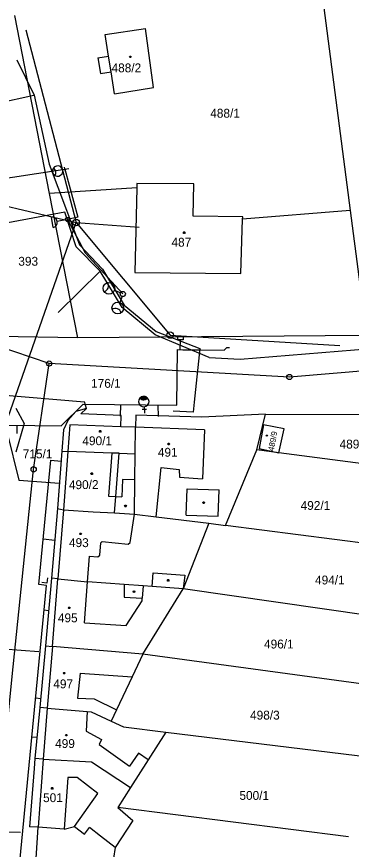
# Model space of a CAD drawing. Extents: x -639621 to -639329, y -1192893 to -1192488.
# Drawn here: x -639497.3 to -639433, y -1192813.4 to -1192653.7 of the extents above; entities that cross this region are included whole.
import ezdxf

# ---------------------------------------------------------------- set-up
doc = ezdxf.new("R2010")
doc.units = 0
for name, color, linetype in [('Vrstva 1', 7, 'Continuous'), ('Vrstva 19', 7, 'Continuous'), ('Vrstva 2', 7, 'Continuous'), ('Vrstva 20', 7, 'Continuous'), ('Vrstva 21', 7, 'Continuous'), ('Vrstva 22', 7, 'Continuous'), ('Vrstva 24', 7, 'Continuous'), ('Vrstva 25', 7, 'Continuous'), ('Vrstva 4', 7, 'Continuous'), ('Vrstva 5', 7, 'Continuous')]:
    doc.layers.add(name, color=color, linetype=linetype)

msp = doc.modelspace()

# ---------------------------------------------------------------- linework, layer by layer
at = {"layer": 'Vrstva 1'}
for p, q in [((-639439.54, -1192642.21), (-639433.22, -1192690.86)), ((-639490.92, -1192687.58), (-639497.61, -1192653.45)), ((-639480.26, -1192657.1), (-639472.54, -1192655.97)), ((-639470.96, -1192667.29), (-639472.54, -1192655.97)), ((-639479.61, -1192661.25), (-639480.26, -1192657.1)), ((-639481.67, -1192661.58), (-639479.61, -1192661.25)), ((-639481.67, -1192661.58), (-639481.19, -1192664.63)), ((-639481.19, -1192664.63), (-639479.13, -1192664.31)), ((-639478.46, -1192668.51), (-639479.13, -1192664.31)), ((-639478.46, -1192668.51), (-639470.96, -1192667.29)), ((-639474.2, -1192686.51), (-639490.92, -1192687.58)), ((-639474.18, -1192685.67), (-639474.2, -1192686.51)), ((-639463.27, -1192685.77), (-639474.18, -1192685.67)), ((-639463.37, -1192691.93), (-639463.27, -1192685.77)), ((-639485.5, -1192715.26), (-639490.92, -1192687.58)), ((-639453.87, -1192692.08), (-639463.37, -1192691.93)), ((-639433.22, -1192690.86), (-639453.88, -1192692.51)), ((-639433.22, -1192690.86), (-639430.11, -1192714.81)), ((-639453.88, -1192692.51), (-639453.87, -1192692.08)), ((-639485.5, -1192715.26), (-639500.89, -1192715.05)), ((-639430.11, -1192714.81), (-639485.5, -1192715.26)), ((-639501.84, -1192726.06), (-639484.21, -1192727.56)), ((-639483.84, -1192728.82), (-639484.21, -1192727.56)), ((-639497.38, -1192728.76), (-639495.79, -1192731.74)), ((-639485.89, -1192729.44), (-639487.46, -1192731.13)), ((-639483.84, -1192728.82), (-639485.89, -1192729.44)), ((-639484.96, -1192729.88), (-639483.84, -1192728.82)), ((-639477.18, -1192730.19), (-639484.96, -1192729.88)), ((-639477.27, -1192732.34), (-639477.18, -1192730.19)), ((-639474.39, -1192730.12), (-639474.46, -1192732.44)), ((-639461.71, -1192730.47), (-639474.39, -1192730.12)), ((-639449.52, -1192729.95), (-639461.71, -1192730.47)), ((-639451.15, -1192736.79), (-639449.52, -1192729.95)), ((-639449.52, -1192729.95), (-639428.21, -1192730.01)), ((-639495.79, -1192731.74), (-639497.4, -1192737.18)), ((-639487.46, -1192731.13), (-639488.23, -1192732.93)), ((-639488.23, -1192732.93), (-639488.56, -1192737.03)), ((-639474.46, -1192732.44), (-639477.27, -1192732.34)), ((-639474.51, -1192737.54), (-639474.46, -1192732.44)), ((-639449.89, -1192731.98), (-639450.7, -1192736.53)), ((-639445.94, -1192732.75), (-639449.89, -1192731.98)), ((-639446.92, -1192737.34), (-639445.94, -1192732.75)), ((-639450.7, -1192736.53), (-639446.92, -1192737.34)), ((-639488.56, -1192737.03), (-639489.43, -1192748.02)), ((-639488.56, -1192737.03), (-639487.41, -1192737.07)), ((-639478.97, -1192737.38), (-639487.41, -1192737.07)), ((-639477.57, -1192737.43), (-639478.97, -1192737.38)), ((-639478.21, -1192745.71), (-639477.57, -1192737.43)), ((-639474.56, -1192742.54), (-639474.51, -1192737.54)), ((-639457.18, -1192751.25), (-639451.15, -1192736.79)), ((-639446.92, -1192737.34), (-639451.15, -1192736.79)), ((-639420.45, -1192740.76), (-639446.92, -1192737.34)), ((-639474.62, -1192749.07), (-639474.56, -1192742.54)), ((-639478.46, -1192748.87), (-639478.21, -1192745.71)), ((-639489.43, -1192748.02), (-639490.57, -1192761.34)), ((-639489.43, -1192748.02), (-639488.29, -1192748.27)), ((-639488.29, -1192748.27), (-639482.55, -1192748.66)), ((-639482.55, -1192748.66), (-639478.46, -1192748.87)), ((-639478.46, -1192748.87), (-639474.62, -1192749.07)), ((-639474.62, -1192749.07), (-639470.47, -1192749.61)), ((-639470.47, -1192749.61), (-639460.35, -1192750.84)), ((-639460.35, -1192750.84), (-639465.28, -1192763.39)), ((-639460.35, -1192750.84), (-639457.18, -1192751.25)), ((-639422.16, -1192755.8), (-639457.18, -1192751.25)), ((-639490.57, -1192761.34), (-639491.69, -1192774.35)), ((-639489.32, -1192761.47), (-639490.57, -1192761.34)), ((-639489.32, -1192761.47), (-639483.65, -1192762.07)), ((-639476.6, -1192762.58), (-639483.65, -1192762.07)), ((-639472.96, -1192762.84), (-639476.6, -1192762.58)), ((-639473.03, -1192775.94), (-639465.28, -1192763.39)), ((-639471.23, -1192762.96), (-639472.96, -1192762.84)), ((-639465.28, -1192763.39), (-639471.23, -1192762.96)), ((-639423.61, -1192769.39), (-639465.28, -1192763.39)), ((-639491.69, -1192774.35), (-639492.8, -1192786.16)), ((-639491.69, -1192774.35), (-639490.4, -1192774.46)), ((-639473.03, -1192775.94), (-639490.4, -1192774.46)), ((-639473.03, -1192775.94), (-639475.11, -1192780.31)), ((-639425.4, -1192782.45), (-639473.03, -1192775.94)), ((-639475.11, -1192780.31), (-639478.12, -1192786.62)), ((-639492.8, -1192786.16), (-639493.73, -1192795.97)), ((-639491.37, -1192786.28), (-639492.8, -1192786.16)), ((-639491.37, -1192786.28), (-639483.72, -1192786.91)), ((-639483.72, -1192786.91), (-639482.92, -1192786.98)), ((-639482.92, -1192786.98), (-639479.14, -1192788.77)), ((-639478.12, -1192786.62), (-639479.14, -1192788.77)), ((-639479.14, -1192788.77), (-639476.76, -1192789.89)), ((-639476.76, -1192789.89), (-639468.6, -1192790.89)), ((-639468.6, -1192790.89), (-639472.03, -1192796.23)), ((-639468.6, -1192790.89), (-639420.82, -1192796.76)), ((-639493.73, -1192795.97), (-639493.91, -1192797.87)), ((-639492.15, -1192796.06), (-639493.73, -1192795.97)), ((-639492.15, -1192796.06), (-639482.87, -1192796.56)), ((-639482.87, -1192796.56), (-639475.39, -1192801.48)), ((-639472.03, -1192796.23), (-639475.39, -1192801.48)), ((-639493.91, -1192797.87), (-639494.79, -1192809.03)), ((-639475.39, -1192801.48), (-639477.86, -1192805.33)), ((-639477.86, -1192805.33), (-639474.95, -1192807.86)), ((-639433.54, -1192810.98), (-639477.86, -1192805.33)), ((-639474.95, -1192807.86), (-639478.34, -1192813)), ((-639493.12, -1192809.14), (-639494.79, -1192809.03)), ((-639494.4, -1192827.84), (-639493.12, -1192809.14)), ((-639478.34, -1192813), (-639481.06, -1192829.36))]:
    msp.add_line(p, q, dxfattribs=at)
at = {"layer": 'Vrstva 19'}
for points in [[(-639355.75, -1192712.63), (-639405.3, -1192719.5), (-639444.91, -1192722.8), (-639491, -1192720.22), (-639511.44, -1192713.33)], [(-639498.88, -1192834.04), (-639503.12, -1192829.95), (-639498.12, -1192780.2), (-639493.99, -1192740.51), (-639491, -1192720.22)]]:
    msp.add_lwpolyline(points, dxfattribs=at)
for centre in [(-639491, -1192720.22), (-639444.91, -1192722.8), (-639493.99, -1192740.51)]:
    msp.add_circle(centre, 0.5, dxfattribs=at)
at = {"layer": 'Vrstva 20'}
for points in [[(-639495.51, -1192656.21), (-639485.82, -1192693.16)], [(-639509.77, -1192687.52), (-639485.82, -1192693.16)], [(-639500.78, -1192735.77), (-639485.82, -1192693.16)], [(-639485.83, -1192693.15), (-639467.78, -1192714.75)], [(-639485.82, -1192693.16), (-639473.73, -1192694.06)], [(-639467.78, -1192714.75), (-639435.22, -1192716.73)]]:
    msp.add_lwpolyline(points, dxfattribs=at)
for centre in [(-639485.82, -1192693.16), (-639467.78, -1192714.75)]:
    msp.add_circle(centre, 0.62, dxfattribs=at)
at = {"layer": 'Vrstva 21'}
for points in [[(-639497.23, -1192661.98), (-639493.87, -1192668.77), (-639490.99, -1192681.96), (-639487.71, -1192690.82), (-639485.18, -1192697.44), (-639480.79, -1192702.15), (-639476.64, -1192709.03), (-639470.46, -1192714.1), (-639462.07, -1192717.33), (-639463.18, -1192727.64)], [(-639463.18, -1192727.64), (-639463.38, -1192729.53), (-639467.23, -1192729.37)]]:
    msp.add_lwpolyline(points, dxfattribs=at)
at = {"layer": 'Vrstva 22'}
for p, q in [((-639488.44, -1192683.03), (-639487.24, -1192682.79)), ((-639487.89, -1192683.37), (-639488.06, -1192682.54)), ((-639487.88, -1192692.68), (-639489.47, -1192692.98)), ((-639487.49, -1192692.58), (-639484.1, -1192699)), ((-639484.1, -1192699), (-639476.89, -1192706.87)), ((-639477.34, -1192706.64), (-639478.49, -1192706.18)), ((-639477.02, -1192707.35), (-639477.44, -1192708.52)), ((-639473.61, -1192726.87), (-639472.15, -1192726.85)), ((-639473.47, -1192726.74), (-639472.27, -1192726.72)), ((-639472.27, -1192726.96), (-639473.44, -1192726.98)), ((-639472.42, -1192726.61), (-639473.29, -1192726.61)), ((-639473.29, -1192726.61), (-639473.28, -1192727.08)), ((-639473.28, -1192727.08), (-639472.42, -1192727.06)), ((-639473.09, -1192726.55), (-639473.05, -1192727.13)), ((-639472.61, -1192726.55), (-639473.06, -1192726.56)), ((-639472.86, -1192726.54), (-639472.85, -1192727.16)), ((-639472.6, -1192727.15), (-639472.61, -1192726.55)), ((-639472.42, -1192727.06), (-639472.42, -1192726.61)), ((-639472.27, -1192726.72), (-639472.27, -1192726.96)), ((-639473.05, -1192727.13), (-639472.6, -1192727.15)), ((-639472.75, -1192728.5), (-639472.74, -1192729.72)), ((-639473.19, -1192728.97), (-639472.34, -1192728.97))]:
    msp.add_line(p, q, dxfattribs=at)
for points in [[(-639503.01, -1192690.37), (-639503.57, -1192685.33), (-639487.98, -1192682.94)], [(-639487.98, -1192682.93), (-639485.53, -1192692.16), (-639487.49, -1192692.58)], [(-639490.65, -1192692.16), (-639490.28, -1192694.12)]]:
    msp.add_lwpolyline(points, dxfattribs=at)
for centre, radius in [((-639487.49, -1192692.58), 0.4), ((-639479.54, -1192705.79), 1.12), ((-639476.89, -1192706.87), 0.5), ((-639477.85, -1192709.56), 1.12)]:
    msp.add_circle(centre, radius, dxfattribs=at)
for centre, radius, start, end in [((-639489.39, -1192683.31), 1, 238.9018, 238.054), ((-639490.71, -1192683.59), 1, 324.1058, 60.0135), ((-639490.46, -1192693.14), 1, 10.7156, 100.7156), ((-639490.46, -1192693.14), 1, 280.7156, 10.7156), ((-639480.73, -1192705.31), 1.12, 282.4447, 33.157), ((-639478.28, -1192710.77), 1.12, 15.2433, 125.9557), ((-639472.85, -1192727.51), 1, 138.1032, 137.2554), ((-639472.88, -1192726.16), 1, 223.3072, 319.2149)]:
    msp.add_arc(centre, radius, start, end, dxfattribs=at)
at = {"layer": 'Vrstva 24'}
for p, q in [((-639465.86, -1192717.55), (-639465.84, -1192715.65)), ((-639477.34, -1192730.33), (-639477.27, -1192728.09)), ((-639470.06, -1192730.34), (-639470.08, -1192728.17)), ((-639497.18, -1192733.61), (-639497.16, -1192732.07)), ((-639492.99, -1192762.57), (-639490.69, -1192738.71)), ((-639490.69, -1192738.71), (-639488.71, -1192738.94)), ((-639492.14, -1192753.8), (-639489.95, -1192754.11)), ((-639497.84, -1192828.49), (-639491.5, -1192762.76)), ((-639491.5, -1192762.76), (-639492.99, -1192762.57)), ((-639491.95, -1192767.45), (-639491.11, -1192767.56)), ((-639493.58, -1192784.31), (-639492.59, -1192784.42)), ((-639494.3, -1192791.81), (-639493.31, -1192791.88))]:
    msp.add_line(p, q, dxfattribs=at)
for points in [[(-639515.87, -1192709.9), (-639519.84, -1192721.02), (-639516.94, -1192722.05), (-639506.44, -1192723.65), (-639501.22, -1192727.82), (-639498.84, -1192732.05), (-639488.74, -1192732.16), (-639484.49, -1192728.01), (-639466.5, -1192728.21)], [(-639466.31, -1192715.65), (-639466.3, -1192715.05), (-639465.3, -1192715.06), (-639465.31, -1192715.66), (-639466.31, -1192715.65)], [(-639466.5, -1192728.21), (-639466.36, -1192717.55), (-639457.42, -1192717.66), (-639456.89, -1192717.15), (-639456.39, -1192717.16)], [(-639465.36, -1192717.56), (-639457.42, -1192717.66), (-639456.89, -1192717.15), (-639456.39, -1192717.16)]]:
    msp.add_lwpolyline(points, dxfattribs=at)
at = {"layer": 'Vrstva 25'}
for p, q in [((-639493.98, -1192668.81), (-639508.15, -1192671.96)), ((-639489.28, -1192710.42), (-639481.2, -1192702.48)), ((-639454.38, -1192719.35), (-639371.54, -1192712.72)), ((-639460.28, -1192719.08), (-639454.38, -1192719.35)), ((-639499.05, -1192733.48), (-639496.86, -1192742.59)), ((-639496.86, -1192742.59), (-639489.05, -1192743.18)), ((-639491.31, -1192761.32), (-639491.43, -1192762.32)), ((-639491.43, -1192762.32), (-639492.43, -1192762.21)), ((-639499.78, -1192774.9), (-639492.99, -1192775.4)), ((-639503.1, -1192809.83), (-639496.5, -1192810.09))]:
    msp.add_line(p, q, dxfattribs=at)
msp.add_lwpolyline([(-639460.28, -1192719.08), (-639470.7, -1192714.68), (-639477.01, -1192709.49), (-639481.2, -1192702.48), (-639485.83, -1192697.85), (-639487.99, -1192691.19), (-639504.1, -1192694.19)], dxfattribs=at)
at = {"layer": 'Vrstva 4'}
for p, q in [((-639479.13, -1192664.31), (-639479.61, -1192661.25)), ((-639474.2, -1192686.51), (-639474.54, -1192702.75)), ((-639454.21, -1192702.93), (-639453.88, -1192692.51)), ((-639474.54, -1192702.75), (-639454.21, -1192702.93)), ((-639487.02, -1192731.99), (-639487.41, -1192737.07)), ((-639477.27, -1192732.34), (-639487.02, -1192731.99)), ((-639461.21, -1192732.93), (-639474.46, -1192732.44)), ((-639461.21, -1192732.93), (-639461.57, -1192742.35)), ((-639487.41, -1192737.07), (-639488.29, -1192748.27)), ((-639478.97, -1192737.38), (-639479.61, -1192745.66)), ((-639477.57, -1192737.43), (-639474.51, -1192737.54)), ((-639470.47, -1192749.61), (-639469.51, -1192740.17)), ((-639469.51, -1192740.17), (-639466.04, -1192740.52)), ((-639466.04, -1192740.52), (-639466, -1192742)), ((-639476.96, -1192742.45), (-639477.08, -1192745.75)), ((-639474.56, -1192742.54), (-639476.96, -1192742.45)), ((-639466, -1192742), (-639461.57, -1192742.35)), ((-639464.7, -1192749.28), (-639464.52, -1192744.24)), ((-639464.52, -1192744.24), (-639458.41, -1192744.46)), ((-639458.59, -1192749.49), (-639458.41, -1192744.46)), ((-639479.61, -1192745.66), (-639478.21, -1192745.71)), ((-639478.21, -1192745.71), (-639477.08, -1192745.75)), ((-639488.29, -1192748.27), (-639489.32, -1192761.47)), ((-639475.47, -1192754.52), (-639474.62, -1192749.07)), ((-639464.7, -1192749.28), (-639458.59, -1192749.49)), ((-639481.27, -1192756.93), (-639481.08, -1192754.59)), ((-639481.08, -1192754.59), (-639480.81, -1192754.36)), ((-639480.81, -1192754.36), (-639475.85, -1192754.82)), ((-639475.85, -1192754.82), (-639475.47, -1192754.52)), ((-639483.65, -1192762.07), (-639483.25, -1192757.16)), ((-639483.25, -1192757.16), (-639481.64, -1192757.26)), ((-639481.64, -1192757.26), (-639481.27, -1192756.93)), ((-639471.23, -1192762.96), (-639471.07, -1192760.35)), ((-639471.07, -1192760.35), (-639464.98, -1192760.78)), ((-639490.4, -1192774.46), (-639489.32, -1192761.47)), ((-639484.24, -1192769.96), (-639483.65, -1192762.07)), ((-639464.98, -1192760.78), (-639465.28, -1192763.39)), ((-639476.6, -1192762.58), (-639476.63, -1192765.03)), ((-639472.96, -1192762.84), (-639473.14, -1192765.21)), ((-639476.63, -1192765.03), (-639473.14, -1192765.21)), ((-639473.18, -1192765.74), (-639473.14, -1192765.21)), ((-639476.21, -1192770.44), (-639473.18, -1192765.74)), ((-639484.24, -1192769.96), (-639476.21, -1192770.44)), ((-639490.4, -1192774.46), (-639491.37, -1192786.28)), ((-639485.08, -1192779.59), (-639485.56, -1192784.4)), ((-639485.08, -1192779.59), (-639475.11, -1192780.31)), ((-639485.56, -1192784.4), (-639482.37, -1192784.49)), ((-639482.37, -1192784.49), (-639478.12, -1192786.62)), ((-639491.37, -1192786.28), (-639492.15, -1192796.06)), ((-639483.72, -1192786.91), (-639483.93, -1192790.72)), ((-639483.93, -1192790.72), (-639480.97, -1192792.33)), ((-639480.97, -1192792.33), (-639481.4, -1192793.29)), ((-639481.4, -1192793.29), (-639475.59, -1192797.41)), ((-639473.84, -1192794.95), (-639475.59, -1192797.41)), ((-639472.03, -1192796.23), (-639473.84, -1192794.95)), ((-639492.15, -1192796.06), (-639493.12, -1192809.14)), ((-639487.4, -1192799.57), (-639488.13, -1192809.47)), ((-639485.63, -1192799.61), (-639487.4, -1192799.57)), ((-639481.64, -1192802.68), (-639485.63, -1192799.61)), ((-639486.14, -1192808.97), (-639481.64, -1192802.68)), ((-639488.13, -1192809.47), (-639493.12, -1192809.14)), ((-639488.13, -1192809.47), (-639486.14, -1192808.97)), ((-639486.14, -1192808.97), (-639484.23, -1192810.44)), ((-639484.23, -1192810.44), (-639483.28, -1192809.2)), ((-639481.19, -1192810.81), (-639483.28, -1192809.2)), ((-639478.34, -1192813), (-639481.19, -1192810.81))]:
    msp.add_line(p, q, dxfattribs=at)
at = {"layer": 'Vrstva 5'}
for points in [[(-639475.35, -1192661.26), (-639475.26, -1192661.41), (-639475.35, -1192661.56), (-639475.53, -1192661.56), (-639475.62, -1192661.41), (-639475.53, -1192661.26)], [(-639465.01, -1192694.95), (-639464.92, -1192695.1), (-639465.01, -1192695.25), (-639465.19, -1192695.25), (-639465.28, -1192695.1), (-639465.19, -1192694.95)], [(-639481.13, -1192733.06), (-639481.04, -1192733.21), (-639481.13, -1192733.36), (-639481.31, -1192733.36), (-639481.4, -1192733.21), (-639481.31, -1192733.06)], [(-639449.2, -1192733.93), (-639449.14, -1192734.03), (-639449.2, -1192734.13), (-639449.32, -1192734.13), (-639449.38, -1192734.03), (-639449.32, -1192733.93)], [(-639467.99, -1192735.49), (-639467.9, -1192735.64), (-639467.99, -1192735.79), (-639468.17, -1192735.79), (-639468.26, -1192735.64), (-639468.17, -1192735.49)], [(-639482.75, -1192741.16), (-639482.66, -1192741.31), (-639482.75, -1192741.46), (-639482.93, -1192741.46), (-639483.02, -1192741.31), (-639482.93, -1192741.16)], [(-639476.27, -1192747.4), (-639476.18, -1192747.55), (-639476.27, -1192747.7), (-639476.45, -1192747.7), (-639476.54, -1192747.55), (-639476.45, -1192747.4)], [(-639461.27, -1192746.73), (-639461.18, -1192746.88), (-639461.27, -1192747.03), (-639461.45, -1192747.03), (-639461.54, -1192746.88), (-639461.45, -1192746.73)], [(-639484.9, -1192752.71), (-639484.81, -1192752.86), (-639484.9, -1192753.01), (-639485.08, -1192753.01), (-639485.17, -1192752.86), (-639485.08, -1192752.71)], [(-639468.09, -1192761.63), (-639468, -1192761.78), (-639468.09, -1192761.93), (-639468.27, -1192761.93), (-639468.36, -1192761.78), (-639468.27, -1192761.63)], [(-639474.65, -1192763.8), (-639474.56, -1192763.95), (-639474.65, -1192764.1), (-639474.83, -1192764.1), (-639474.92, -1192763.95), (-639474.83, -1192763.8)], [(-639487.07, -1192766.9), (-639486.98, -1192767.05), (-639487.07, -1192767.2), (-639487.25, -1192767.2), (-639487.34, -1192767.05), (-639487.25, -1192766.9)], [(-639488.04, -1192779.43), (-639487.95, -1192779.58), (-639488.04, -1192779.73), (-639488.22, -1192779.73), (-639488.31, -1192779.58), (-639488.22, -1192779.43)], [(-639487.62, -1192791.32), (-639487.53, -1192791.47), (-639487.62, -1192791.62), (-639487.8, -1192791.62), (-639487.89, -1192791.47), (-639487.8, -1192791.32)], [(-639490.35, -1192801.5), (-639490.26, -1192801.65), (-639490.35, -1192801.8), (-639490.53, -1192801.8), (-639490.62, -1192801.65), (-639490.53, -1192801.5)]]:
    msp.add_lwpolyline(points, close=True, dxfattribs=at)

# ---------------------------------------------------------------- texts
at = {"layer": 'Vrstva 2'}
for s, p in [('488/2', (-639479.04, -1192664.37)), ('488/1', (-639460.1, -1192673.07)), ('487', (-639467.54, -1192697.8)), ('393', (-639496.93, -1192701.46)), ('176/1', (-639482.97, -1192724.86)), ('490/1', (-639484.64, -1192735.87)), ('489/1', (-639435.28, -1192736.51)), ('715/1', (-639496.08, -1192738.39)), ('491', (-639470.15, -1192738.08)), ('492/1', (-639442.76, -1192748.28)), ('493', (-639487.21, -1192755.41)), ('494/1', (-639439.99, -1192762.57)), ('495', (-639489.34, -1192769.83)), ('496/1', (-639449.78, -1192774.85)), ('497', (-639490.22, -1192782.49)), ('498/3', (-639452.46, -1192788.48)), ('499', (-639489.87, -1192793.93)), ('500/1', (-639454.5, -1192803.88)), ('501', (-639492.18, -1192804.31))]:
    msp.add_text(s, height=1.7, dxfattribs=at).set_placement(p)
for s, height, rotation, p in [('489/9', 1.14, 79.2974, (-639447.91, -1192737.08)), ('490/2', 1.7, 0.7448, (-639487.21, -1192744.32))]:
    msp.add_text(s, height=height, rotation=rotation, dxfattribs=at).set_placement(p)

doc.saveas('drawing.dxf')
